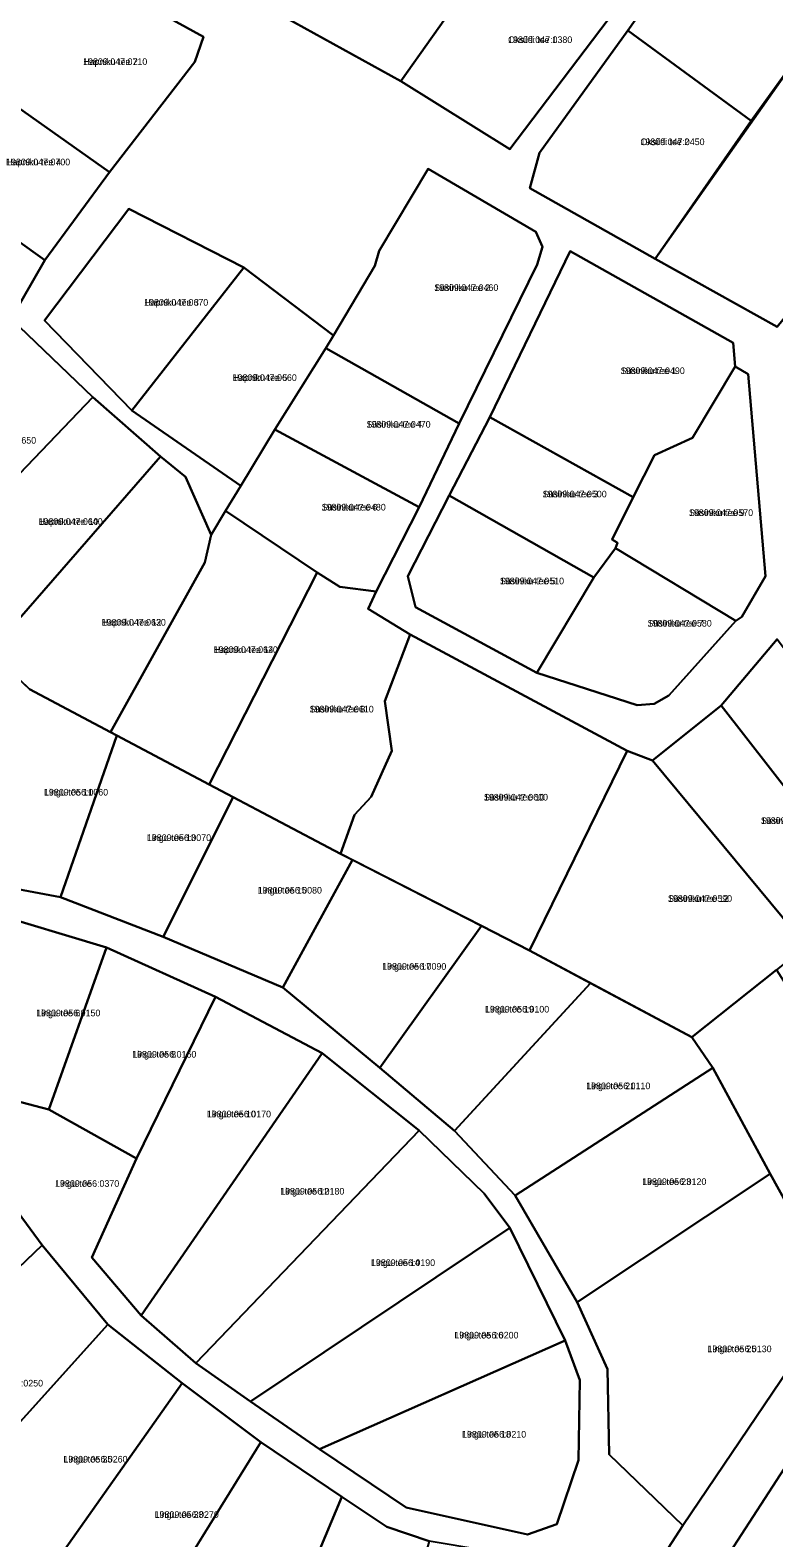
# Model space of a CAD drawing. Extents: x 516875 to 535633, y 6574491 to 6593094.
# Drawn here: x 521809.5 to 521977.7, y 6587757.1 to 6588097.9 of the extents above; entities that cross this region are included whole.
import ezdxf

# ---------------------------------------------------------------- set-up
doc = ezdxf.new("R2010")
doc.units = 0
for name, color, linetype in [('L_AADRESS', 7, 'Continuous'), ('PIIR', 7, 'Continuous'), ('TUNNUS', 7, 'Continuous')]:
    doc.layers.add(name, color=color, linetype=linetype)

msp = doc.modelspace()

# ---------------------------------------------------------------- linework, layer by layer
at = {"layer": 'PIIR'}
for points in [[(521907.71, 6588106.69), (521893.34, 6588086.36), (521864.91, 6588102.09), (521882.77, 6588125.18)], [(521941.9, 6588102.55), (521917.98, 6588071.01), (521893.34, 6588086.36), (521907.71, 6588106.69), (521917.06, 6588119.15)], [(521987.51, 6588098.39), (521986.11, 6588096.1), (521972.57, 6588077.42), (521944.66, 6588097.83), (521959.43, 6588118.64)], [(521818.6, 6588112.98), (521848.71, 6588096.4), (521846.75, 6588090.75), (521827.48, 6588065.82), (521796.66, 6588087.52), (521795.86, 6588088.77), (521814.19, 6588114.28)], [(521972.57, 6588077.42), (521950.91, 6588046.25), (521922.54, 6588062.23), (521924.74, 6588070.17), (521944.66, 6588097.83)], [(522015.31, 6588076.21), (521978.5, 6588030.89), (521950.91, 6588046.25), (521986.11, 6588096.1)], [(521796.66, 6588087.52), (521827.48, 6588065.82), (521812.85, 6588045.94), (521780.64, 6588068.91), (521795.86, 6588088.77)], [(521812.85, 6588045.94), (521805.2, 6588032.65), (521798.65, 6588025.32), (521765.62, 6588048.73), (521780.64, 6588068.91)], [(521923.87, 6588052.33), (521925.41, 6588048.91), (521924.18, 6588044.94), (521906.52, 6588008.99), (521876.39, 6588026.02), (521878.1, 6588028.9), (521887.44, 6588044.61), (521888.47, 6588048.01), (521899.5, 6588066.59)], [(521857.81, 6588044.28), (521832.52, 6588011.93), (521812.74, 6588032.32), (521831.85, 6588057.56)], [(521971.94, 6588020.19), (521968.99, 6588021.92), (521968.5, 6588027.24), (521931.64, 6588047.98), (521913.48, 6588010.45), (521904.26, 6587992.71), (521894.92, 6587974.46), (521896.67, 6587967.5), (521924.1, 6587952.61), (521946.77, 6587945.35), (521950.62, 6587945.66), (521953.94, 6587947.51), (521969.09, 6587964.39), (521970.47, 6587965.28), (521975.86, 6587974.47)], [(521968.5, 6588027.24), (521968.99, 6588021.92), (521959.35, 6588005.8), (521950.72, 6588001.87), (521945.88, 6587992.37), (521913.48, 6588010.45), (521931.64, 6588047.98)], [(521878.1, 6588028.9), (521876.39, 6588026.02), (521864.85, 6588007.68), (521857.17, 6587994.89), (521832.52, 6588011.93), (521857.81, 6588044.28)], [(521823.69, 6588014.98), (521783.86, 6587973.44), (521769.04, 6587988.02), (521798.65, 6588025.32), (521805.2, 6588032.65)], [(521906.52, 6588008.99), (521897.48, 6587990.11), (521864.85, 6588007.68), (521876.39, 6588026.02)], [(521971.94, 6588020.19), (521975.86, 6587974.47), (521970.47, 6587965.28), (521969.09, 6587964.39), (521941.87, 6587980.85), (521942.34, 6587982.01), (521941.17, 6587982.76), (521945.88, 6587992.37), (521950.72, 6588001.87), (521959.35, 6588005.8), (521968.99, 6588021.92)], [(521838.97, 6588001.54), (521801.33, 6587958.48), (521800.96, 6587956.92), (521783.86, 6587973.44), (521823.69, 6588014.98)], [(521897.48, 6587990.11), (521887.75, 6587971), (521879.52, 6587972.12), (521874.42, 6587975.3), (521853.72, 6587989.26), (521857.17, 6587994.89), (521864.85, 6588007.68)], [(521945.88, 6587992.37), (521941.17, 6587982.76), (521942.34, 6587982.01), (521941.87, 6587980.85), (521937.04, 6587974.16), (521904.26, 6587992.71), (521913.48, 6588010.45)], [(521844.66, 6587996.98), (521850.42, 6587983.82), (521849.02, 6587977.62), (521827.64, 6587939.27), (521809.38, 6587948.92), (521800.96, 6587956.92), (521801.33, 6587958.48), (521838.97, 6588001.54)], [(521937.04, 6587974.16), (521924.1, 6587952.61), (521896.67, 6587967.5), (521894.92, 6587974.46), (521904.26, 6587992.71)], [(521874.42, 6587975.3), (521850, 6587927.44), (521829.1, 6587938.5), (521827.64, 6587939.27), (521849.02, 6587977.62), (521850.42, 6587983.82), (521853.72, 6587989.26)], [(521969.09, 6587964.39), (521953.94, 6587947.51), (521950.62, 6587945.66), (521946.77, 6587945.35), (521924.1, 6587952.61), (521937.04, 6587974.16), (521941.87, 6587980.85)], [(521879.52, 6587972.12), (521887.75, 6587971), (521885.93, 6587967.12), (521895.43, 6587961.33), (521889.76, 6587946.27), (521891.29, 6587935.01), (521886.63, 6587924.6), (521882.88, 6587920.58), (521879.71, 6587911.72), (521850, 6587927.44), (521874.42, 6587975.3)], [(521944.55, 6587935.02), (521922.47, 6587889.89), (521911.61, 6587895.44), (521879.71, 6587911.72), (521882.88, 6587920.58), (521886.63, 6587924.6), (521891.29, 6587935.01), (521889.76, 6587946.27), (521895.43, 6587961.33)], [(522001.14, 6587930.06), (522006.43, 6587921.27), (522013.58, 6587914.11), (521999.3, 6587902.28), (521965.81, 6587945.26), (521978.46, 6587960.29)], [(521806.44, 6587951.71), (521809.38, 6587948.92), (521827.64, 6587939.27), (521829.1, 6587938.5), (521816.38, 6587901.93), (521796.19, 6587905.69)], [(521999.3, 6587902.28), (521994.99, 6587898.82), (521985.07, 6587890.85), (521950.29, 6587932.81), (521965.81, 6587945.26)], [(521829.1, 6587938.5), (521850, 6587927.44), (521855.46, 6587924.55), (521839.6, 6587892.94), (521816.38, 6587901.93)], [(521950.29, 6587932.81), (521985.07, 6587890.85), (521978.31, 6587885.48), (521959.17, 6587870.27), (521922.47, 6587889.89), (521944.55, 6587935.02)], [(521855.46, 6587924.55), (521879.71, 6587911.72), (521882.41, 6587910.34), (521866.66, 6587881.5), (521839.6, 6587892.94)], [(521882.41, 6587910.34), (521911.61, 6587895.44), (521888.57, 6587863.37), (521866.66, 6587881.5)], [(521912.23, 6587834.96), (521897.52, 6587849.21), (521875.53, 6587866.66), (521851.44, 6587879.43), (521826.8, 6587890.56), (521799.66, 6587898.72), (521762.92, 6587903), (521766.04, 6587886.19), (521782.84, 6587866.52), (521794.96, 6587858.82), (521813.75, 6587853.93), (521833.56, 6587842.85), (521823.43, 6587820.49), (521834.62, 6587807.37), (521846.95, 6587796.57), (521859.34, 6587787.92), (521874.92, 6587777.18), (521894.55, 6587763.98), (521922.03, 6587757.85), (521928.62, 6587760.2), (521933.51, 6587774.66), (521933.8, 6587792.73), (521930.52, 6587801.71), (521917.97, 6587827.17)], [(521826.8, 6587890.56), (521813.75, 6587853.93), (521794.96, 6587858.82), (521799.66, 6587898.72)], [(521888.57, 6587863.37), (521911.61, 6587895.44), (521922.47, 6587889.89), (521936.23, 6587882.53), (521905.45, 6587849.14)], [(521826.8, 6587890.56), (521851.44, 6587879.43), (521833.56, 6587842.85), (521813.75, 6587853.93)], [(521963.94, 6587863.34), (521959.17, 6587870.27), (521978.31, 6587885.48), (521998.81, 6587853.37), (522011.74, 6587844.22), (521992.16, 6587811.71), (521976.87, 6587839.43)], [(521963.94, 6587863.34), (521919.19, 6587834.52), (521905.45, 6587849.14), (521936.23, 6587882.53), (521959.17, 6587870.27)], [(521823.43, 6587820.49), (521833.56, 6587842.85), (521851.44, 6587879.43), (521875.53, 6587866.66), (521834.62, 6587807.37)], [(521834.62, 6587807.37), (521875.53, 6587866.66), (521897.52, 6587849.21), (521846.95, 6587796.57)], [(521976.87, 6587839.43), (521933.27, 6587810.42), (521919.19, 6587834.52), (521963.94, 6587863.34)], [(521846.95, 6587796.57), (521897.52, 6587849.21), (521912.23, 6587834.96), (521917.97, 6587827.17), (521859.34, 6587787.92)], [(521753.74, 6587800.59), (521797.76, 6587842.89), (521812.25, 6587823.28), (521768.76, 6587781.72)], [(521940.47, 6587775.96), (521940.06, 6587795.22), (521933.27, 6587810.42), (521976.87, 6587839.43), (521992.16, 6587811.71), (521957.13, 6587759.89)], [(521859.34, 6587787.92), (521917.97, 6587827.17), (521930.52, 6587801.71), (521874.92, 6587777.18)], [(521774.14, 6587774.96), (521768.76, 6587781.72), (521812.25, 6587823.28), (521827.08, 6587805.34), (521790.2, 6587764.52)], [(521790.2, 6587764.52), (521827.08, 6587805.34), (521843.85, 6587792.09), (521813.64, 6587749.28)], [(521874.92, 6587777.18), (521930.52, 6587801.71), (521933.8, 6587792.73), (521933.51, 6587774.66), (521928.62, 6587760.2), (521922.03, 6587757.85), (521894.55, 6587763.98)], [(521813.64, 6587749.28), (521843.85, 6587792.09), (521861.7, 6587778.76), (521834.91, 6587735.46)], [(521861.7, 6587778.76), (521880.02, 6587766.4), (521860.16, 6587719.05), (521834.91, 6587735.46)], [(522014.39, 6587756.34), (521999.62, 6587733.38), (521967.73, 6587753.77), (521980.96, 6587774.11), (521983.66, 6587774.51)], [(521880.02, 6587766.4), (521890.21, 6587759.62), (521899.72, 6587756.38), (521884.65, 6587703.12), (521860.16, 6587719.05)]]:
    msp.add_lwpolyline(points, close=True, dxfattribs=at)
for points in [[(521959.43, 6588118.64), (521944.66, 6588097.83), (521924.74, 6588070.17), (521922.54, 6588062.23), (521950.91, 6588046.25), (521978.5, 6588030.89), (522015.31, 6588076.21), (522030.73, 6588098.49)], [(521978.46, 6587960.29), (521965.81, 6587945.26), (521950.29, 6587932.81), (521944.55, 6587935.02), (521895.43, 6587961.33), (521885.93, 6587967.12), (521887.75, 6587971), (521897.48, 6587990.11), (521906.52, 6588008.99), (521924.18, 6588044.94), (521925.41, 6588048.91), (521923.87, 6588052.33), (521899.5, 6588066.59), (521888.47, 6588048.01), (521887.44, 6588044.61), (521878.1, 6588028.9), (521857.81, 6588044.28), (521831.85, 6588057.56), (521812.74, 6588032.32), (521832.52, 6588011.93), (521857.17, 6587994.89), (521853.72, 6587989.26), (521850.42, 6587983.82), (521844.66, 6587996.98), (521838.97, 6588001.54), (521823.69, 6588014.98), (521805.2, 6588032.65), (521812.85, 6588045.94), (521827.48, 6588065.82), (521846.75, 6588090.75), (521848.71, 6588096.4), (521818.6, 6588112.98)], [(521864.91, 6588102.09), (521893.34, 6588086.36), (521917.98, 6588071.01), (521941.9, 6588102.55)], [(521940.87, 6587734.77), (521957.13, 6587759.89), (521992.16, 6587811.71), (522011.74, 6587844.22), (522031.82, 6587877.34), (522045.48, 6587901.21), (522061.87, 6587930.4), (522076.84, 6587956.5), (522087.37, 6587975.22), (522096.86, 6587969.92), (522092.63, 6587962.87), (522075.92, 6587935), (522059.83, 6587907.39), (522045.99, 6587883.49), (522044.08, 6587878.05), (522040.48, 6587874.24), (522030.03, 6587855.16), (522015.16, 6587829.39), (521999.29, 6587803.43), (521984.5, 6587778.84), (521980.96, 6587774.11), (521967.73, 6587753.77)], [(521796.19, 6587905.69), (521816.38, 6587901.93), (521839.6, 6587892.94), (521866.66, 6587881.5), (521888.57, 6587863.37), (521905.45, 6587849.14), (521919.19, 6587834.52), (521933.27, 6587810.42), (521940.06, 6587795.22), (521940.47, 6587775.96), (521957.13, 6587759.89), (521940.87, 6587734.77), (521923.6, 6587752.34), (521899.72, 6587756.38), (521890.21, 6587759.62), (521880.02, 6587766.4), (521861.7, 6587778.76), (521843.85, 6587792.09), (521827.08, 6587805.34), (521812.25, 6587823.28), (521797.76, 6587842.89)]]:
    msp.add_lwpolyline(points, dxfattribs=at)

# ---------------------------------------------------------------- texts
at = {"layer": 'L_AADRESS'}
for s, p in [('Oksiidi tee 1', (521917.62, 6588095.01)), ('Hapniku tee 2', (521821.49, 6588090.05)), ('Oksiidi tee 2', (521947.55, 6588071.93)), ('Hapniku tee 4', (521804.06, 6588067.36)), ('Süsiniku tee 2', (521900.9, 6588038.97)), ('Hapniku tee 3', (521835.28, 6588035.63)), ('Süsiniku tee 1', (521943.07, 6588020.18)), ('Hapniku tee 5', (521855.31, 6588018.63)), ('Süsiniku tee 4', (521885.58, 6588008.07)), ('Süsiniku tee 3', (521925.41, 6587992.3)), ('Süsiniku tee 6', (521875.43, 6587989.34)), ('Hapniku tee 10', (521811.41, 6587986.1)), ('Süsiniku tee 9', (521958.52, 6587988.1)), ('Süsiniku tee 5', (521915.76, 6587972.66)), ('Hapniku tee 12', (521825.69, 6587963.32)), ('Süsiniku tee 7', (521949.17, 6587963.1)), ('Hapniku tee 14', (521851.03, 6587957.14)), ('Süsiniku tee 8', (521872.71, 6587943.69)), ('Lingu tee 11', (521812.64, 6587924.91)), ('Süsiniku tee 10', (521912.13, 6587923.78)), ('Süsiniku tee 14', (521974.79, 6587918.49)), ('Lingu tee 13', (521835.92, 6587914.63)), ('Lingu tee 15', (521861, 6587902.75)), ('Süsiniku tee 12', (521953.77, 6587900.88)), ('Lingu tee 17', (521889.13, 6587885.53)), ('Lingu tee 6', (521810.88, 6587875.01)), ('Lingu tee 19', (521912.4, 6587875.86)), ('Lingu tee 8', (521832.59, 6587865.67)), ('Lingu tee 21', (521935.28, 6587858.53)), ('Lingu tee 10', (521849.48, 6587852.16)), ('Lingu tee', (521815.15, 6587836.46)), ('Lingu tee 23', (521947.95, 6587836.88)), ('Lingu tee 12', (521866.07, 6587834.71)), ('Lingu tee 14', (521886.6, 6587818.57)), ('Lingu tee 16', (521905.46, 6587802.18)), ('Lingu tee 25', (521962.71, 6587799.08)), ('Lingu tee 18', (521907.2, 6587779.78)), ('Lingu tee 35', (521817.03, 6587774.14)), ('Lingu tee 33', (521837.67, 6587761.63))]:
    msp.add_text(s, height=1.5, dxfattribs=at).set_placement(p)
at = {"layer": 'TUNNUS'}
for s, p in [('19809:047:0380', (521917.62, 6588095.01)), ('19809:047:0710', (521821.49, 6588090.05)), ('19809:047:0450', (521947.55, 6588071.93)), ('19809:047:0700', (521804.06, 6588067.36)), ('19809:047:0460', (521900.9, 6588038.97)), ('19809:047:0670', (521835.28, 6588035.63)), ('19809:047:0490', (521943.07, 6588020.18)), ('19809:047:0660', (521855.31, 6588018.63)), ('19809:047:0470', (521885.58, 6588008.07)), ('19809:047:0650', (521796.36, 6588004.46)), ('19809:047:0500', (521925.41, 6587992.3)), ('19809:047:0480', (521875.43, 6587989.34)), ('19809:047:0640', (521811.41, 6587986.1)), ('19809:047:0570', (521958.52, 6587988.1)), ('19809:047:0510', (521915.76, 6587972.66)), ('19809:047:0630', (521825.69, 6587963.32)), ('19809:047:0580', (521949.17, 6587963.1)), ('19809:047:0620', (521851.03, 6587957.14)), ('19809:047:0610', (521872.71, 6587943.69)), ('19809:056:0060', (521812.64, 6587924.91)), ('19809:047:0600', (521912.13, 6587923.78)), ('19809:047:0560', (521974.79, 6587918.49)), ('19809:056:0070', (521835.92, 6587914.63)), ('19809:056:0080', (521861, 6587902.75)), ('19809:047:0590', (521953.77, 6587900.88)), ('19809:056:0090', (521889.13, 6587885.53)), ('19809:056:0150', (521810.88, 6587875.01)), ('19809:056:0100', (521912.4, 6587875.86)), ('19809:056:0160', (521832.59, 6587865.67)), ('19809:056:0110', (521935.28, 6587858.53)), ('19809:056:0170', (521849.48, 6587852.16)), ('19809:056:0370', (521815.15, 6587836.46)), ('19809:056:0120', (521947.95, 6587836.88)), ('19809:056:0180', (521866.07, 6587834.71)), ('19809:056:0190', (521886.6, 6587818.57)), ('19809:056:0200', (521905.46, 6587802.18)), ('19809:056:0130', (521962.71, 6587799.08)), ('19809:056:0250', (521797.92, 6587791.33)), ('19809:056:0210', (521907.2, 6587779.78)), ('19809:056:0260', (521817.03, 6587774.14)), ('19809:056:0270', (521837.67, 6587761.63))]:
    msp.add_text(s, height=1.5, dxfattribs=at).set_placement(p)

doc.saveas('drawing.dxf')
